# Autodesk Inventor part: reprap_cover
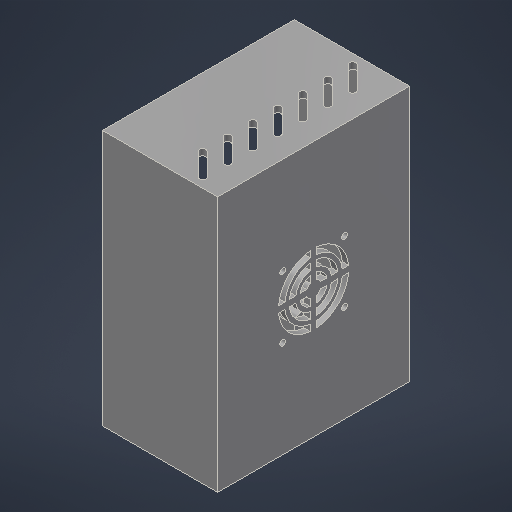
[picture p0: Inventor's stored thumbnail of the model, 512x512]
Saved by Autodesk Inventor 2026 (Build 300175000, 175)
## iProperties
Created: 2025-04
Part Number: reprap_cover
Material: 1.0037 S235JR
Document SubType Name: Modeling
Designer: BennF
Density: 7.85 g/cm^3
Appearance: Stahl
Author: BennF
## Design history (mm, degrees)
sketch "Sketch2"
  geometry: L1 (-45, 60)-(45, 60); L2 (45, 60)-(45, -60); L3 (45, -60)-(-45, -60); L4 (-45, -60)-(-45, 60); 3 further points
  constraints: 8 end point, 2 midpoint, 2 parallel, 1 horizontal, 1 horizontal alignment, 1 perpendicular, 1 vertical alignment
  dimensions: "d0" = 90 distance of L1.start L1.end; "d1" = 120 distance of L3.end L1.start
extrude "Extrusion1" new body sketch "Sketch2" distance "d2" = 3; taper "d3" = 0 deg
sketch "Sketch3"
  geometry: L1 (-60, -45)-(-60, 45) reference; L2 (60, -45)-(-60, -45) reference; L3 (60, 45)-(60, -45) reference; L4 (-60, 45)-(60, 45) reference; L5 (57, -42)-(-57, -42); L6 (-57, -42)-(-57, 42); L7 (-57, 42)-(57, 42); L8 (57, 42)-(57, -42); 1 further point
  constraints: 8 end point, 3 other
  dimensions: "d4" = 3 distance between parallel lines of L3 L8
extrude "Extrusion2" join sketch "Sketch3" distance "d5" = 51; taper "d6" = 0 deg
sketch "Sketch4"
  geometry: L1 (57, 42)-(57, -42) reference; L2 (-57, 42)-(57, 42) reference; L3 (57, -42)-(-57, -42) reference; L4 (-57, -42)-(-57, 42) reference; L5 (58, -43)-(58, 43); L6 (58, 43)-(-58, 43); L7 (-58, 43)-(-58, -43); L8 (-58, -43)-(58, -43); 1 further point
  constraints: 8 end point, 3 other
  dimensions: "d7" = 1 distance between parallel lines of L1 L5
extrude "Extrusion3" cut sketch "Sketch4" distance "d8" = 1; taper "d9" = 0 deg
sketch "Sketch5"
  geometry: L1 (-14.5, -14.5)-(14.5, -14.5); L2 (14.5, -14.5)-(14.5, 14.5); L3 (14.5, 14.5)-(-14.5, 14.5); L4 (-14.5, 14.5)-(-14.5, -14.5); 5 further points
  constraints: 8 end point, 2 coincident, 2 midpoint, 2 parallel, 2 perpendicular, 1 horizontal, 1 horizontal alignment, 1 vertical alignment
  dimensions: "d17" = 29 distance of L3.end L1.start
hole "Hole1" sketch "Sketch5" at (-14.5, -14.5), (-14.5, 14.5), (14.5, 14.5), (14.5, -14.5) diameter "d10" = 2.7; stored, may be unused: countersink angle "d14" = 90 deg, drill point angle "d16" = 118 deg; dims "d11" = 6, "d12" = 4, "d13" = 2, "d15" = 8
sketch "Sketch6" dims "d18" = 33
  geometry: L1 (-13.5, 0)-(-16.5, 0); L2 (-13.5, 0)-(-11.5, 0); L3 (-11.5, 0)-(-8.5, 0); L4 (-8.5, 0)-(-6.5, 0); L5 (-6.5, 0)-(-3.5, 0); L6 (-1.5, -3.162)-(-1.5, -16.432); L7 (1.5, -3.162)-(1.5, -16.432); L8 (-16.432, -1.5)-(-3.162, -1.5); L9 (-16.432, 1.5)-(-3.162, 1.5); L10 (-1.5, 3.162)-(-1.5, 16.432); L11 (1.5, 3.162)-(1.5, 16.432); L12 (3.162, -1.5)-(16.432, -1.5); L13 (3.162, 1.5)-(16.432, 1.5); L14 (-1.5, -3.162)-(1.5, -3.162); L15 (-3.162, -1.5)-(-3.162, 1.5); 41 further points
  constraints: 30 end point, 6 coincident, 6 horizontal, 6 vertical alignment, 5 horizontal alignment, 4 equal length, 2 midpoint, 2 perpendicular, 2 point on line, 2 vertical, 34 other
  dimensions: "d19" = 3 distance of L1.start L1.end; "d20" = 2 distance of L1.start L2.end; "d21" = 3 distance of L8.end L9.end
extrude "Extrusion4" cut sketch "Sketch6" stored distance "d22" = 56; taper "d23" = 0 deg
sketch "Sketch7"
  geometry: L1 (-11.5, 4.5)-(-22.107, 15.107); L2 (-10.439, 5.561)-(-21.046, 16.167); L3 (-23.167, 14.046)-(-12.561, 3.439); L4 (-11.5, 16.232)-(-22.107, 26.839); L5 (-10.439, 17.293)-(-21.046, 27.899); L6 (-23.167, 25.778)-(-12.561, 15.172); L7 (-11.5, 27.964)-(-22.107, 38.571); L8 (-10.439, 29.025)-(-21.046, 39.632); L9 (-23.167, 37.51)-(-12.561, 26.904); L10 (-11.5, 39.697)-(-22.107, 50.303); L11 (-10.439, 40.757)-(-21.046, 51.364); L12 (-23.167, 49.243)-(-12.561, 38.636); L13 (-16.803, 9.803)-(-16.803, 21.536); L14 (-16.803, 21.536)-(-16.803, 33.268); L15 (-16.803, 33.268)-(-16.803, 45); L16 (-11.5, 51.429)-(-22.107, 62.036); L17 (-10.439, 52.49)-(-21.046, 63.096); L18 (-23.167, 60.975)-(-12.561, 50.368); L19 (-11.5, 63.161)-(-22.107, 73.768); L20 (-10.439, 64.222)-(-21.046, 74.828); L21 (-23.167, 72.707)-(-12.561, 62.101); L22 (-11.5, 74.893)-(-22.107, 85.5); L23 (-10.439, 75.954)-(-21.046, 86.561); L24 (-23.167, 84.439)-(-12.561, 73.833); L25 (-16.803, 45)-(-16.803, 56.732); L26 (-16.803, 56.732)-(-16.803, 68.464); L27 (-16.803, 68.464)-(-16.803, 80.197); L28 (-3, 3)-(-53, 3) reference; L29 (-3, 87)-(-53, 87) reference; L30 (0, 90)-(0, 0) reference; A1 r 1.5 centre (-11.5, 4.5) between (-12.561, 3.439) and (-10.439, 5.561); A2 r 1.5 centre (-22.107, 15.107) between (-21.046, 16.167) and (-23.167, 14.046); A3 r 1.5 centre (-11.5, 16.232) between (-12.561, 15.172) and (-10.439, 17.293); A4 r 1.5 centre (-22.107, 26.839) between (-21.046, 27.899) and (-23.167, 25.778); A5 r 1.5 centre (-11.5, 27.964) between (-12.561, 26.904) and (-10.439, 29.025); A6 r 1.5 centre (-22.107, 38.571) between (-21.046, 39.632) and (-23.167, 37.51); A7 r 1.5 centre (-11.5, 39.697) between (-12.561, 38.636) and (-10.439, 40.757); A8 r 1.5 centre (-22.107, 50.303) between (-21.046, 51.364) and (-23.167, 49.243); A9 r 1.5 centre (-11.5, 51.429) between (-12.561, 50.368) and (-10.439, 52.49); A10 r 1.5 centre (-22.107, 62.036) between (-21.046, 63.096) and (-23.167, 60.975); A11 r 1.5 centre (-11.5, 63.161) between (-12.561, 62.101) and (-10.439, 64.222); A12 r 1.5 centre (-22.107, 73.768) between (-21.046, 74.828) and (-23.167, 72.707); A13 r 1.5 centre (-11.5, 74.893) between (-12.561, 73.833) and (-10.439, 75.954); A14 r 1.5 centre (-22.107, 85.5) between (-21.046, 86.561) and (-23.167, 84.439); 1 further point
  constraints: 68 end point, 30 tangent, 29 equal length, 28 point on circle, 14 centre point, 7 midpoint, 6 equal radius, 6 vertical alignment, 2 vertical
  dimensions: "d25" = 3 distance between parallel lines of L2 L3; "d26" = 15 distance of L1.start L1.end; "d27" = 45 deg angle of L28 L1; "d28" = 11.5 distance from line of L30 L1.start (computed from d25)
extrude "Extrusion5" cut sketch "Sketch7" extent not by distance; stored distance "d29" = 0; taper "d30" = 0 deg
sketch "Sketch8"
  geometry: L1 (24.75, 46.643)-(34.75, 46.643); L2 (34.75, 46.643)-(34.75, 68.643); L3 (34.75, 68.643)-(24.75, 68.643); L4 (24.75, 68.643)-(24.75, 46.643); L5 (54, 90)-(0, 90) reference; L6 (53, 2)-(53, 88) reference; 3 further points
  constraints: 8 end point, 2 midpoint, 2 parallel, 1 horizontal, 1 perpendicular
  dimensions: "d31" = 22 distance of L3.end L1.start; "d32" = 10 distance of L1.start L1.end; "d33" = 32.357 distance from line of L5 point (24.75, 57.643); "d34" = 23.25 distance from line of L6 point (29.75, 68.643)
extrude "Extrusion6" cut sketch "Sketch8" stored distance "d35" = 10; taper "d36" = 0 deg
sketch "Sketch9"
  geometry: L1 (57, -42)-(57, 42) reference; L2 (-57, -42)-(57, -42) reference; L3 (57, 42)-(-57, 42) reference; L4 (-57, 42)-(-57, -42) reference; L5 (-49, 38)-(-49, 42); L6 (-53, 34)-(-57, 34); L7 (49, -38)-(49, -42); L8 (53, -34)-(57, -34); C1 r 2 at (53, -38); C2 r 2 at (-53, 38); A1 r 4 centre (53, -38) between (49, -38) and (53, -34); A2 r 4 centre (-53, 38) between (-49, 38) and (-53, 34); 1 further point
  constraints: 8 end point, 8 tangent, 4 centre point, 4 perpendicular, 4 point on circle, 4 point on line, 2 coincident, 2 equal radius
  dimensions: "d37" = 4 diameter of C1; "d38" = 2 radial gap between concentric circles of C1 A1
extrude "Extrusion7" join sketch "Sketch9" distance "d39" = 10; taper "d40" = 0 deg
body "Solid1"
node "Projected Loop1"
